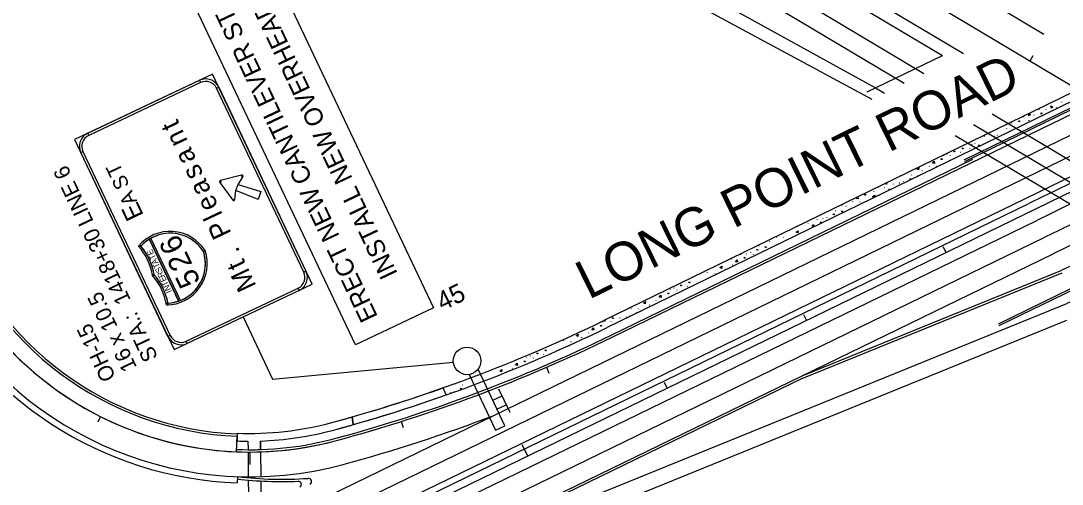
# Model space of a CAD drawing. Extents: x 2338610 to 2351914, y 366540 to 376484.
# Drawn here: x 2348627 to 2349299, y 367825 to 368124 of the extents above; entities that cross this region are included whole.
import ezdxf

# ---------------------------------------------------------------- set-up
doc = ezdxf.new("R2010")
doc.units = 0
for name, color, linetype in [('RD_HC_Cl', 7, 'Continuous'), ('RD_HC_CL_Rel', 7, 'Continuous'), ('RD_PD_Final_LnLine', 7, 'Continuous'), ('RD_PD_Final_TrvlWay', 7, 'Continuous'), ('RD_PD_FOC', 7, 'Continuous'), ('RD_PD_GrRail', 7, 'Continuous'), ('RD_PD_MedBWall', 7, 'Continuous'), ('RD_PD_PaveShd', 7, 'Continuous'), ('RD_PD_SW', 7, 'Continuous'), ('TR PM UNASSIGNED 3', 7, 'Continuous'), ('TR SN EXTRUDED PANEL SIGNS - GROUND MOUNTED', 7, 'Continuous'), ('TR SN EXTRUDED PANEL SIGNS- MOUNTED OVERHEAD', 7, 'Continuous'), ('TR SN UNASSIGNED 4', 7, 'Continuous'), ('TR SN UNASSIGNED 7', 7, 'Continuous')]:
    doc.layers.add(name, color=color, linetype=linetype)

msp = doc.modelspace()

# ---------------------------------------------------------------- linework, layer by layer
at = {"layer": 'RD_HC_Cl'}
for p, q in [((2346281.57, 369885.43), (2351112.4, 367003.22)), ((2348794.11, 367765.14), (2349441.47, 368080.05))]:
    msp.add_line(p, q, dxfattribs=at)
at = {"layer": 'RD_HC_CL_Rel'}
for centre, radius, start, end in [((2348774.65, 368059.29), 214.01, 62.97341, 174.06692), ((2348774.63, 368059.29), 213.99, 174.06692, 285.16043), ((2348566.46, 368827.6), 1010, 285.16043, 295.94073)]:
    msp.add_arc(centre, radius, start, end, dxfattribs=at)
at = {"layer": 'RD_PD_Final_LnLine'}
for p, q in [((2348577.88, 368466.48), (2349209.46, 368089.66)), ((2349076.83, 368154.82), (2349196.76, 368083.27)), ((2349253.37, 368063.47), (2351090.88, 366967.15)), ((2348932.13, 367868.98), (2349312.02, 368053.77)), ((2349241.51, 368056.57), (2349846.26, 367695.75)), ((2348784.92, 367784.02), (2349317.27, 368042.98)), ((2348790.17, 367773.23), (2349322.52, 368032.19)), ((2348791.92, 367769.63), (2349276.99, 368005.6)), ((2348797.17, 367758.84), (2349282.24, 367994.81)), ((2348802.42, 367748.05), (2349287.49, 367984.01)), ((2349130.88, 367894.48), (2349292.74, 367973.22)), ((2348773.54, 367845.31), (2348773.68, 367829.31)), ((2348781.54, 367845.42), (2348781.68, 367829.41))]:
    msp.add_line(p, q, dxfattribs=at)
for radius, start, end in [(5729.58, 109.588035, 115.940729), (5717.58, 109.58804, 115.94073), (5705.58, 109.58804, 115.94073), (5693.58, 110.25944, 115.94073)]:
    msp.add_arc((2351783.35, 362853.29), radius, start, end, dxfattribs=at)
at = {"layer": 'RD_PD_Final_TrvlWay'}
for p, q in [((2348878.36, 368246.49), (2349178.28, 368080.32)), ((2349008.27, 367919.36), (2349341.05, 368081.24)), ((2349178.28, 368080.32), (2349184.05, 368076.87)), ((2349229.65, 368049.67), (2349840.11, 367685.45)), ((2349130.88, 367894.48), (2349297.99, 367962.43)), ((2348969.53, 367816), (2349130.88, 367894.48)), ((2348779.67, 367794.81), (2348932.13, 367868.98))]:
    msp.add_line(p, q, dxfattribs=at)
for centre, radius, start, end in [((2348774.64, 368059.31), 230, 61.0108, 285.1623), ((2348774.64, 368059.31), 214, 61.0108, 285.16043), ((2351783.35, 362853.29), 5681.58, 111.03168, 115.94073), ((2348566.46, 368827.6), 1010, 285.16118, 295.94073), ((2348566.46, 368827.6), 1026, 285.16158, 290.87974), ((2348795.32, 368069.44), 241.69, 263.22259, 274.00942), ((2348812.54, 367826.37), 2, 295.94073, 99.24034)]:
    msp.add_arc(centre, radius, start, end, dxfattribs=at)
at = {"layer": 'RD_PD_FOC'}
for p, q in [((2349007.62, 367920.71), (2349240.94, 368034.21)), ((2349131.44, 367893.09), (2349298.55, 367961.04)), ((2348970.19, 367814.65), (2349131.53, 367893.14))]:
    msp.add_line(p, q, dxfattribs=at)
for centre, radius, start, end in [((2348774.64, 368059.31), 202.5, 62.97341, 267.67657), ((2348566.46, 368827.6), 1008.5, 285.16118, 295.94073), ((2348774.64, 368059.31), 212.5, 267.6974, 285.16043), ((2348795.32, 368069.44), 243.19, 263.213, 272.47556), ((2348805.91, 367824.48), 2, 298.48553, 92.47556)]:
    msp.add_arc(centre, radius, start, end, dxfattribs=at)
at = {"layer": 'RD_PD_GrRail'}
for p, q in [((2349038.24, 368219.76), (2349234.87, 368102.45)), ((2349286.8, 368114.85), (2349135.79, 368204.98)), ((2349176.03, 368072.84), (2348958.64, 368190.22))]:
    msp.add_line(p, q, dxfattribs=at)
at = {"layer": 'RD_PD_MedBWall'}
for p, q in [((2349235.32, 368033.93), (2349537.7, 368181.41)), ((2349235.87, 368032.8), (2349538.23, 368180.27)), ((2349257.43, 367928.02), (2349446.22, 368020.07)), ((2349257.98, 367926.9), (2349446.77, 368018.94))]:
    msp.add_line(p, q, dxfattribs=at)
at = {"layer": 'RD_PD_PaveShd'}
for p, q in [((2348586.11, 368480.2), (2349221.38, 368101.18)), ((2349172.91, 368077.72), (2349221.38, 368101.18)), ((2348766.05, 367845.48), (2348766.45, 367855.47)), ((2348766.63, 367829.45), (2348766.49, 367825.45))]:
    msp.add_line(p, q, dxfattribs=at)
for radius, start, end in [(234, 81.2484, 268.00355), (204, 61.0108, 267.6974)]:
    msp.add_arc((2348774.64, 368059.31), radius, start, end, dxfattribs=at)
at = {"layer": 'RD_PD_SW'}
for p, q in [((2349389.83, 368118.81), (2349003.02, 367930.15)), ((2349392.39, 368114.49), (2349005.21, 367925.65)), ((2349283.98, 368066.08), (2349284, 368066.35)), ((2349288.33, 368066.4), (2349288.36, 368066.67)), ((2349294.79, 368067.92), (2349294.9, 368067.69)), ((2349298.41, 368071.13), (2349298.43, 368071.4)), ((2349273.9, 368061.35), (2349273.92, 368061.62)), ((2349277.18, 368062.19), (2349276.88, 368063.71)), ((2349277.35, 368059.14), (2349277.37, 368059.42)), ((2349280.36, 368062.87), (2349280.47, 368062.64)), ((2349256.12, 368053.25), (2349256.16, 368053.61)), ((2349262.91, 368054.09), (2349262.93, 368054.36)), ((2349265.92, 368057.82), (2349266.03, 368057.59)), ((2349248.48, 368049.04), (2349248.5, 368049.31)), ((2349254.77, 368049.12), (2349254.93, 368049)), ((2349256.78, 368049.76), (2349256.94, 368049.64)), ((2349233, 368038.72), (2349233.23, 368038.88)), ((2349238.92, 368041.33), (2349238.93, 368041.13)), ((2349240.34, 368044.07), (2349240.5, 368043.95)), ((2349242.35, 368044.71), (2349242.51, 368044.59)), ((2349247.92, 368044.03), (2349247.93, 368044.14)), ((2349222.03, 368036.79), (2349222.25, 368036.95)), ((2349224.49, 368037.72), (2349224.5, 368037.52)), ((2349226.27, 368036.59), (2349226.28, 368036.39)), ((2349208.39, 368026.77), (2349208.61, 368026.92)), ((2349212.72, 368029.65), (2349212.95, 368029.8)), ((2349217.51, 368029.73), (2349217.41, 368029.5)), ((2349193.56, 368018.93), (2349193.79, 368019.09)), ((2349196.02, 368019.86), (2349196.03, 368019.66)), ((2349196.66, 368024.59), (2349196.61, 368024.48)), ((2349201.5, 368023.99), (2349201.72, 368024.15)), ((2349205.46, 368023.32), (2349205.38, 368023.34)), ((2349177.01, 368013.7), (2349177.02, 368013.5)), ((2349183.74, 368015.84), (2349183.96, 368016)), ((2349189.66, 368018.45), (2349189.67, 368018.25)), ((2349163.46, 368006.76), (2349163.68, 368006.92)), ((2349165.69, 368008.85), (2349166.54, 368009.9)), ((2349168.25, 368006.84), (2349168.15, 368006.61)), ((2349177.41, 368009.64), (2349176.35, 368010.16)), ((2349152.24, 368001.11), (2349152.46, 368001.27)), ((2349159.12, 368003.88), (2349159.35, 368004.04)), ((2349134.48, 367992.96), (2349134.7, 367993.11)), ((2349140.39, 367995.56), (2349140.4, 367995.36)), ((2349144.3, 367996.05), (2349144.52, 367996.2)), ((2349146.76, 367996.97), (2349146.77, 367996.77)), ((2349148.54, 367995.84), (2349148.55, 367995.64)), ((2349127.74, 367990.82), (2349127.75, 367990.62)), ((2349102.97, 367978.23), (2349103.2, 367978.38)), ((2349109.86, 367981), (2349110.08, 367981.16)), ((2349114.2, 367983.88), (2349114.42, 367984.04)), ((2349118.99, 367983.96), (2349118.88, 367983.73)), ((2349091.13, 367972.68), (2349091.14, 367972.48)), ((2349095.04, 367973.16), (2349095.26, 367973.32)), ((2349097.5, 367974.09), (2349097.51, 367973.89)), ((2349099.28, 367972.96), (2349099.29, 367972.76)), ((2349106.01, 367975.09), (2349106.23, 367975.25)), ((2349085.21, 367970.07), (2349085.44, 367970.23)), ((2349085.73, 367966.02), (2349085.96, 367966.17)), ((2349060.6, 367958.12), (2349060.82, 367958.28)), ((2349069.72, 367961.08), (2349069.62, 367960.85)), ((2349074.51, 367960.36), (2349074.73, 367960.52)), ((2349081.4, 367963.13), (2349081.62, 367963.29)), ((2349056.75, 367952.21), (2349056.97, 367952.36)), ((2349062.67, 367954.82), (2349062.68, 367954.62)), ((2349045.77, 367950.28), (2349046, 367950.44)), ((2349048.23, 367951.21), (2349048.24, 367951.01)), ((2349050.01, 367950.07), (2349050.02, 367949.87)), ((2348962.49, 367803.35), (2349297.85, 367939.71)), ((2349020.46, 367938.2), (2349020.35, 367937.97)), ((2349032.13, 367940.25), (2349032.36, 367940.41)), ((2349036.47, 367943.13), (2349036.69, 367943.29)), ((2349013.4, 367931.93), (2349013.41, 367931.73)), ((2349017.31, 367932.41), (2349017.53, 367932.57)), ((2349019.77, 367933.34), (2349019.78, 367933.14)), ((2349024.11, 367934.87), (2349023.8, 367934.95)), ((2349025.24, 367937.48), (2349025.47, 367937.64)), ((2348973.08, 367796.86), (2349301.62, 367930.44)), ((2349002.33, 367929.28), (2349002.56, 367929.44)), ((2349007.48, 367929.32), (2349007.71, 367929.48)), ((2348988.69, 367919.25), (2348988.92, 367919.41)), ((2348993.03, 367922.13), (2348993.25, 367922.29)), ((2348997.82, 367922.21), (2348997.76, 367922.1)), ((2348973.87, 367911.42), (2348974.09, 367911.57)), ((2348976.33, 367912.34), (2348976.34, 367912.19)), ((2348977.02, 367917.2), (2348976.91, 367916.97)), ((2348981.8, 367916.48), (2348982.03, 367916.64)), ((2348949.16, 367905.91), (2348949.17, 367905.72)), ((2348953.07, 367906.4), (2348953.29, 367906.56)), ((2348955.53, 367907.33), (2348955.54, 367907.13)), ((2348957.31, 367906.19), (2348957.32, 367905.99)), ((2348964.04, 367908.33), (2348964.27, 367908.48)), ((2348969.96, 367910.93), (2348969.97, 367910.73)), ((2348943.24, 367903.31), (2348943.47, 367903.47)), ((2348943.76, 367899.25), (2348943.99, 367899.41)), ((2348901.35, 367882.16), (2348899.47, 367886.8)), ((2348906.27, 367884.44), (2348906.28, 367884.24)), ((2348906.96, 367889.3), (2348906.85, 367889.07)), ((2348911.74, 367888.58), (2348911.96, 367888.74)), ((2348903.81, 367883.52), (2348904.03, 367883.67)), ((2348841.3, 367862.99), (2348840.6, 367867.99)), ((2348840.6, 367867.99), (2348841.3, 367862.99)), ((2348766.43, 367857.47), (2348766.47, 367852.47)), ((2348773.48, 367852.31), (2348773.52, 367846.85)), ((2348773.48, 367852.31), (2348773.52, 367846.85)), ((2348781.47, 367852.42), (2348781.52, 367846.92)), ((2348781.52, 367846.92), (2348781.47, 367852.42)), ((2348773.7, 367827.21), (2348773.77, 367818.7)), ((2348781.7, 367826.63), (2348781.79, 367817.13))]:
    msp.add_line(p, q, dxfattribs=at)
for points in [[(2349291.62, 368067.24), (2349291.3, 368068.81), (2349292.58, 368068.17), (2349291.64, 368067.26)], [(2349270.56, 368058.3), (2349270.64, 368059.06), (2349271.3, 368058.85), (2349270.56, 368058.3)], [(2349276.92, 368063.74), (2349278.14, 368063.12), (2349277.2, 368062.21)], [(2349284.99, 368063.35), (2349285.08, 368064.11), (2349285.74, 368063.9), (2349284.99, 368063.35)], [(2349256.68, 368053.86), (2349256.87, 368053.8), (2349256.12, 368053.25)], [(2349228.52, 368039.33), (2349229.16, 368039.75), (2349229.42, 368039.11), (2349228.52, 368039.33)], [(2349233.85, 368041.21), (2349234.49, 368041.63), (2349234.75, 368040.99), (2349233.85, 368041.21)], [(2349244.7, 368042.46), (2349244.86, 368043.51), (2349245.49, 368042.84)], [(2349214.96, 368031.73), (2349215.96, 368032.98), (2349216.29, 368031.59), (2349214.98, 368031.72)], [(2349220.26, 368034.2), (2349220.9, 368034.63), (2349221.16, 368033.98), (2349220.26, 368034.2)], [(2349226.25, 368033.46), (2349226.95, 368033.89), (2349226.94, 368033.8)], [(2349204.79, 368028.04), (2349206.16, 368028.87), (2349205.99, 368027.45), (2349204.81, 368028.03)], [(2349184.58, 368018.32), (2349185.22, 368018.75), (2349185.49, 368018.11), (2349184.58, 368018.32)], [(2349200.05, 368021.46), (2349200.7, 368021.89), (2349200.96, 368021.24), (2349200.05, 368021.46)], [(2349205.38, 368023.34), (2349206.02, 368023.77), (2349206.08, 368023.62)], [(2349180.05, 368016.49), (2349180.16, 368016.23), (2349179.73, 368016.33)], [(2349186.76, 368014.2), (2349187.49, 368015.11), (2349187.61, 368014.61)], [(2349156.79, 368005.15), (2349156.72, 368004.57), (2349156.17, 368004.84)], [(2349166.72, 368009.99), (2349167.02, 368008.7), (2349165.72, 368008.84)], [(2349170.99, 368011.32), (2349171.63, 368011.74), (2349171.9, 368011.1), (2349170.99, 368011.32)], [(2349176.32, 368010.17), (2349177.69, 368011.01), (2349177.54, 368009.7)], [(2349150.79, 367998.58), (2349151.43, 367999), (2349151.7, 367998.36), (2349150.79, 367998.58)], [(2349156.12, 368000.46), (2349156.76, 368000.88), (2349157.02, 368000.24), (2349156.12, 368000.46)], [(2349137.23, 367990.98), (2349138.23, 367992.23), (2349138.56, 367990.84), (2349137.26, 367990.97)], [(2349142.53, 367993.45), (2349143.17, 367993.88), (2349143.43, 367993.24), (2349142.53, 367993.45)], [(2349117.7, 367986.08), (2349117.76, 367985.82), (2349117.27, 367985.87)], [(2349122.54, 367988.44), (2349122.63, 367988.22), (2349122.27, 367988.31)], [(2349127.06, 367987.29), (2349128.43, 367988.12), (2349128.26, 367986.71), (2349127.08, 367987.28)], [(2349101.53, 367975.7), (2349102.17, 367976.12), (2349102.43, 367975.48), (2349101.53, 367975.7)], [(2349106.85, 367977.58), (2349107.5, 367978), (2349107.76, 367977.36), (2349106.85, 367977.58)], [(2349077.79, 367964.41), (2349079.16, 367965.24), (2349079, 367963.82), (2349077.82, 367964.4)], [(2349087.96, 367968.1), (2349088.97, 367969.35), (2349089.29, 367967.96), (2349087.99, 367968.09)], [(2349093.26, 367970.57), (2349093.9, 367971), (2349094.17, 367970.35), (2349093.26, 367970.57)], [(2349052.26, 367952.81), (2349052.9, 367953.24), (2349053.17, 367952.6), (2349052.26, 367952.81)], [(2349057.59, 367954.69), (2349058.23, 367955.12), (2349058.5, 367954.48), (2349057.59, 367954.69)], [(2349038.7, 367945.21), (2349039.7, 367946.46), (2349040.03, 367945.07), (2349038.73, 367945.21)], [(2349044, 367947.69), (2349044.64, 367948.11), (2349044.9, 367947.47), (2349044, 367947.69)], [(2349028.53, 367941.53), (2349029.9, 367942.36), (2349029.73, 367940.94), (2349028.56, 367941.51)], [(2349008.33, 367931.81), (2349008.97, 367932.24), (2349009.23, 367931.59), (2349008.33, 367931.81)], [(2349023.8, 367934.95), (2349024.44, 367935.37), (2349024.56, 367935.09)], [(2348995.26, 367924.22), (2348996.26, 367925.46), (2348996.59, 367924.07), (2348995.29, 367924.21)], [(2349000.56, 367926.69), (2349001.2, 367927.11), (2349001.46, 367926.47), (2349000.56, 367926.69)], [(2349003, 367929.93), (2349003.64, 367930.36), (2349003.9, 367929.72), (2349003, 367929.93)], [(2349011.23, 367928.59), (2349011.24, 367928.6), (2349011.24, 367928.59)], [(2348985.09, 367920.53), (2348986.46, 367921.36), (2348986.29, 367919.94), (2348985.11, 367920.51)], [(2348964.89, 367910.81), (2348965.53, 367911.24), (2348965.79, 367910.6), (2348964.89, 367910.81)], [(2348980.55, 367914.08), (2348981, 367914.37), (2348981.03, 367914.3)], [(2348959.56, 367908.93), (2348960.2, 367909.36), (2348960.46, 367908.72), (2348959.56, 367908.93)], [(2348935.83, 367897.65), (2348937.2, 367898.48), (2348937.03, 367897.06), (2348935.85, 367897.63)], [(2348946, 367901.33), (2348947, 367902.58), (2348947.33, 367901.19), (2348946.02, 367901.33)], [(2348951.3, 367903.81), (2348951.94, 367904.23), (2348952.2, 367903.59), (2348951.3, 367903.81)], [(2348910.3, 367886.05), (2348910.94, 367886.48), (2348911.2, 367885.83), (2348910.3, 367886.05)], [(2348827.47, 367864.34), (2348827.47, 367864.34)], [(2348766.43, 367857.47), (2348766.43, 367856.97), (2348766.45, 367855.47), (2348766.47, 367852.47)], [(2348828.78, 367859.51), (2348828.78, 367859.51)], [(2348773.52, 367846.85), (2348773.52, 367846.81)]]:
    msp.add_lwpolyline(points, dxfattribs=at)
for centre, radius, start, end in [((2349222.52, 368124.98), 200, 292.12665, 296.14693), ((2348566.46, 368827.6), 998, 285.16118, 295.94073), ((2348566.46, 368827.6), 1003, 285.16118, 295.94073), ((2348566.46, 368827.6), 998, 285.94365, 289.49196), ((2348566.46, 368827.6), 1003, 285.90336, 289.50479), ((2348774.64, 368059.31), 202, 267.66956, 285.16043), ((2348774.64, 368059.31), 202, 267.66956, 285.16038), ((2348566.46, 368827.6), 998, 285.16118, 285.94365), ((2348774.64, 368059.31), 207, 271.89123, 285.16043), ((2348774.64, 368059.31), 207, 271.89123, 285.1604), ((2348566.46, 368827.6), 1003, 285.16118, 285.90336), ((2348566.46, 368827.6), 1003, 285.16117883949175, 285.16118119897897), ((2348774.64, 368059.31), 207, 285.1604, 285.16042), ((2348566.46, 368827.6), 1003, 285.16117598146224, 285.16117883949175), ((2348774.64, 368059.31), 207, 285.16042, 285.16043), ((2348774.64, 368059.31), 207, 267.73815, 269.67674), ((2348774.64, 368059.31), 207, 267.73815, 269.67674), ((2348774.64, 368059.31), 212.5, 269.69809, 271.8554)]:
    msp.add_arc(centre, radius, start, end, dxfattribs=at)
at = {"layer": 'TR SN EXTRUDED PANEL SIGNS - GROUND MOUNTED'}
for p, q in [((2348742.17, 368085.2), (2348742.84, 368083.79)), ((2348753.25, 368080.07), (2348754.66, 368080.74)), ((2348670.78, 368049.66), (2348670.11, 368051.07)), ((2348665.65, 368038.58), (2348667.06, 368039.25)), ((2348755.26, 368019.24), (2348755.89, 368019.7)), ((2348755.89, 368019.7), (2348755.7, 368020.46)), ((2348769.4, 368023.97), (2348769.59, 368023.21)), ((2348769.59, 368023.21), (2348770.25, 368022.79)), ((2348764.27, 368008.31), (2348763.64, 368007.84)), ((2348765.05, 368008.22), (2348764.27, 368008.31)), ((2348703.78, 367978.97), (2348702.9, 367978.19)), ((2348702.9, 367978.19), (2348703.8, 367977.44)), ((2348709.85, 367982.7), (2348728.77, 367942.74)), ((2348729.88, 367943.14), (2348710.86, 367983.3)), ((2348745.8, 367975.27), (2348744.69, 367974.89)), ((2348744.81, 367974.64), (2348745.8, 367975.27)), ((2348712.77, 367959.98), (2348711.89, 367959.21)), ((2348711.89, 367959.21), (2348713.05, 367959.39)), ((2348810.87, 367962.06), (2348809.46, 367961.39)), ((2348805.74, 367950.98), (2348806.41, 367949.57)), ((2348720.87, 367941.39), (2348720.88, 367940.22)), ((2348720.88, 367940.22), (2348722.04, 367940.4)), ((2348723.27, 367920.57), (2348721.86, 367919.9)), ((2348734.35, 367915.44), (2348733.68, 367916.85))]:
    msp.add_line(p, q, dxfattribs=at)
for points in [[(2348814.89, 367953.58), (2348750.64, 368089.22), (2348661.63, 368047.06), (2348725.88, 367911.42), (2348814.89, 367953.58), (2348814.89, 367953.58)], [(2348742.84, 368083.79), (2348670.78, 368049.66), (2348670.11, 368051.07), (2348742.17, 368085.2), (2348742.84, 368083.79), (2348742.84, 368083.79)], [(2348809.46, 367961.39), (2348753.25, 368080.07), (2348754.66, 368080.74), (2348810.87, 367962.06), (2348809.46, 367961.39), (2348809.46, 367961.39)], [(2348667.06, 368039.25), (2348723.27, 367920.57), (2348721.86, 367919.9), (2348665.65, 368038.58), (2348667.06, 368039.25), (2348667.06, 368039.25)], [(2348755.89, 368019.7), (2348755.26, 368019.24), (2348763.64, 368007.84), (2348764.27, 368008.31), (2348765.05, 368008.22), (2348765.67, 368013.98), (2348767.09, 368017.94), (2348770.25, 368022.79), (2348769.59, 368023.21), (2348769.4, 368023.97), (2348755.7, 368020.46), (2348755.89, 368019.7), (2348755.89, 368019.7)], [(2348781.84, 368013.34), (2348780, 368008.19), (2348765.67, 368013.98), (2348767.09, 368017.94), (2348781.84, 368013.34), (2348781.84, 368013.34)], [(2348729.88, 367943.14), (2348710.86, 367983.3), (2348709.8, 367982.8), (2348728.82, 367942.64), (2348729.88, 367943.14), (2348729.88, 367943.14)], [(2348733.68, 367916.85), (2348805.74, 367950.98), (2348806.41, 367949.57), (2348734.35, 367915.44), (2348733.68, 367916.85), (2348733.68, 367916.85)]]:
    msp.add_lwpolyline(points, close=True, dxfattribs=at)
for centre, radius, start, end in [((2348746.18, 368076.72), 9.38, 25.34431, 115.34452), ((2348746.18, 368076.72), 7.82, 25.34431, 115.34452), ((2348674.13, 368042.59), 9.38, 115.34425, 205.34446), ((2348674.13, 368042.59), 7.82, 115.34425, 205.34446), ((2348755.89, 368019.7), 0.782, 104.36379, 216.3249), ((2348769.59, 368023.21), 0.782, 326.89803, 104.36379), ((2348764.27, 368008.31), 0.782, 216.32463, 353.79038), ((2348723.29, 367961.14), 26.58, 32.10063, 140.09744), ((2348723.29, 367961.14), 26.58, 32.10063, 140.09744), ((2348723.29, 367961.14), 25.4, 32.10063, 140.09744), ((2348723.29, 367961.15), 25.4, 32.41289, 119.30882), ((2348674.84, 367953.28), 37.52, 9.08663, 41.60199), ((2348674.84, 367953.28), 37.52, 9.08663, 41.60199), ((2348674.84, 367953.28), 38.69, 9.08663, 41.60199), ((2348723.29, 367961.14), 25.4, 121.94541, 137.85599), ((2348674.78, 367953.35), 38.69, 9.45848, 39.94098), ((2348720.61, 367966.79), 25.4, 270.59118, 18.58799), ((2348720.61, 367966.79), 26.58, 270.59118, 18.58799), ((2348720.61, 367966.79), 26.58, 270.59118, 18.58799), ((2348720.62, 367966.8), 25.4, 291.37981, 18.27573), ((2348683.84, 367934.29), 37.52, 9.08663, 41.60199), ((2348683.84, 367934.29), 37.52, 9.08663, 41.60199), ((2348683.84, 367934.29), 38.69, 9.08663, 41.60199), ((2348683.85, 367934.21), 38.69, 10.74764, 41.23014), ((2348802.39, 367958.04), 7.82, 295.3441, 25.34431), ((2348802.39, 367958.04), 9.38, 295.3441, 25.34431), ((2348720.61, 367966.79), 25.4, 272.83259, 288.74305), ((2348730.34, 367923.91), 9.38, 205.34446, 295.3441), ((2348730.34, 367923.91), 7.82, 205.34446, 295.3441)]:
    msp.add_arc(centre, radius, start, end, dxfattribs=at)
at = {"layer": 'TR SN EXTRUDED PANEL SIGNS- MOUNTED OVERHEAD'}
for p, q in [((2348789.39, 367892.37), (2348905.94, 367903.22)), ((2348935.13, 367886.18), (2348942.28, 367871.09)), ((2348931.31, 367878.79), (2348937.32, 367881.64)), ((2348934.06, 367872.99), (2348940.09, 367875.84))]:
    msp.add_line(p, q, dxfattribs=at)
msp.add_lwpolyline([(2348842.8, 367914.48), (2348699.83, 368216.35), (2348750.13, 368240.18), (2348893.11, 367938.31)], close=True, dxfattribs=at)
for points in [[(2348770.38, 367932.5), (2348789.39, 367892.37)], [(2348916.07, 367895.32), (2348933.11, 367859.34), (2348939.17, 367862.21), (2348921.87, 367898.73)]]:
    msp.add_lwpolyline(points, dxfattribs=at)
msp.add_circle((2348914.8, 367904.14), 8.91, dxfattribs=at)
at = {"layer": 'TR SN UNASSIGNED 7'}
for p, q in [((2349277.88, 368097.75), (2349279.93, 368101.18)), ((2349223.69, 367974.11), (2349221.94, 367977.71)), ((2349133.77, 367930.36), (2349132.02, 367933.96)), ((2348965.99, 367899.98), (2348967.57, 367896.31)), ((2349043.84, 367886.62), (2349042.09, 367890.22)), ((2348678.35, 367868.18), (2348676.55, 367864.61)), ((2348872.34, 367865.03), (2348873.55, 367861.22)), ((2348774.77, 367845.3), (2348774.77, 367837.3)), ((2348953.92, 367842.88), (2348950.42, 367850.07))]:
    msp.add_line(p, q, dxfattribs=at)

# ---------------------------------------------------------------- texts
at = {"layer": 'TR PM UNASSIGNED 3'}
for s, p in [('STA.:  1418+30 LINE 6', (2348715.6, 367906.44)), ('16 x 10.5', (2348702.04, 367900.02)), ('OH-15', (2348688.48, 367893.61))]:
    msp.add_text(s, height=10, rotation=115.32218, dxfattribs=at).set_placement(p)
at = {"layer": 'TR SN EXTRUDED PANEL SIGNS - GROUND MOUNTED'}
for s, height, p in [('t', 12.51, (2348729.83, 368056.47)), ('n', 12.51, (2348734.81, 368045.95)), ('a', 12.51, (2348740.31, 368034.34)), ('T', 9.38, (2348693.25, 368025.95)), ('s', 12.51, (2348744.92, 368024.6)), ('S', 9.38, (2348697.28, 368017.45)), ('a', 12.51, (2348749.87, 368014.16)), ('A', 9.38, (2348702.12, 368007.22)), ('E', 11.72, (2348706.43, 367998.13)), ('e', 12.51, (2348754.59, 368004.18)), ('l', 12.51, (2348757.25, 367998.57)), ('P', 12.51, (2348763.02, 367986.4)), ('6', 14.07, (2348732.76, 367977.24)), ('E', 3.91, (2348712.96, 367973.38)), ('T', 3.91, (2348714.3, 367970.56)), ('2', 14.07, (2348737.93, 367966.31)), ('.', 12.51, (2348768.64, 367974.53)), ('A', 3.91, (2348715.8, 367967.39)), ('T', 3.91, (2348716.92, 367965.02)), ('t', 12.51, (2348772.43, 367966.52)), ('S', 3.91, (2348718.36, 367961.98)), ('R', 3.91, (2348719.8, 367958.95)), ('E', 3.91, (2348721.13, 367956.13)), ('5', 14.07, (2348743.11, 367955.38)), ('M', 12.51, (2348779.08, 367952.48)), ('T', 3.91, (2348722.46, 367953.32)), ('N', 3.91, (2348723.9, 367950.28)), ('I', 3.91, (2348724.56, 367948.9))]:
    msp.add_text(s, height=height, rotation=115.34425, dxfattribs=at).set_placement(p)
at = {"layer": 'TR SN EXTRUDED PANEL SIGNS- MOUNTED OVERHEAD'}
for s, p in [('ERECT NEW CANTILEVER STRUCTURE.', (2348857.44, 367932.65)), ('INSTALL NEW OVERHEAD SIGN(S).', (2348870.25, 367960.36))]:
    msp.add_text(s, height=11.7187, rotation=115.34433, dxfattribs=at).set_placement(p)
at = {"layer": 'TR SN UNASSIGNED 4'}
msp.add_text('LONG POINT ROAD', height=25, rotation=26.15368, dxfattribs=at).set_placement((2348993.19, 367943.41))
at = {"layer": 'TR SN UNASSIGNED 7'}
msp.add_text('45', height=12, rotation=25.94073, dxfattribs=at).set_placement((2348898.83, 367936.18))

doc.saveas('drawing.dxf')
